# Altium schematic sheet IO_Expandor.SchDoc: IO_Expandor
size A3; DocumentNumber: MB1144; Revision: B-02; SheetNumber: 6; SheetTotal: 25; Project: STM32L476G-EVAL
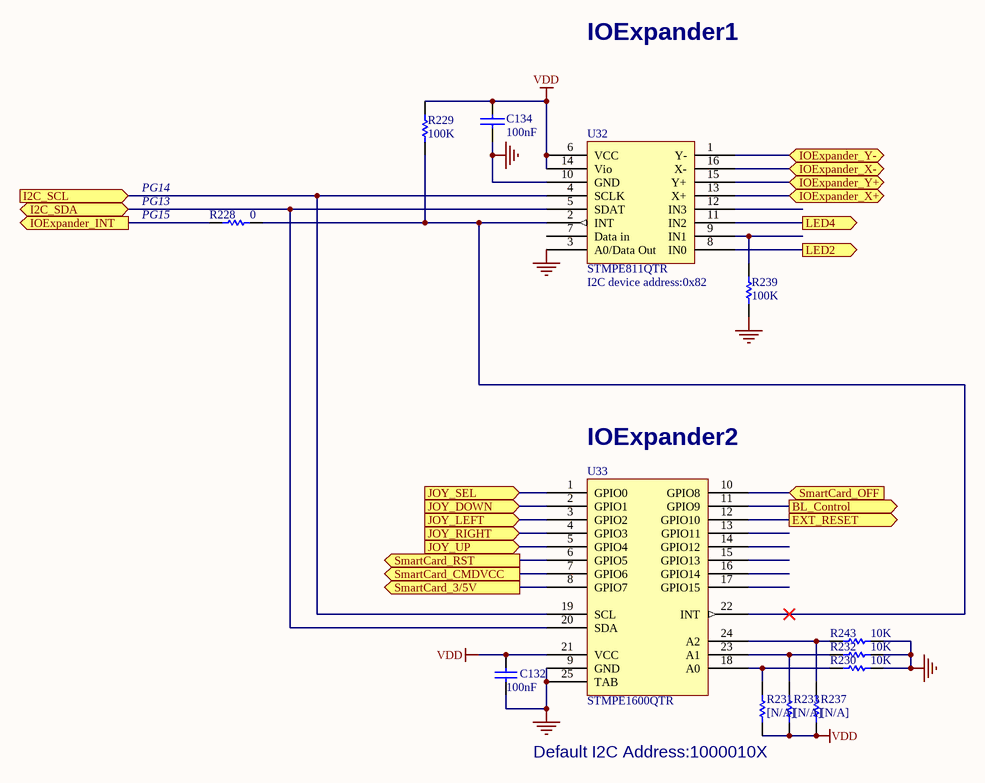
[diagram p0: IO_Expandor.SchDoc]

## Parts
C132  100nF  [0402C]
C134  100nF  [0402C]
R228  0  [0603R]
R229  100K  [0402R]
R230  10K  [0402R]
R231  [N/A]  [0603R]
R232  10K  [0402R]
R233  [N/A]  [0603R]
R237  [N/A]  [0603R]
R239  100K  [0402R]
R243  10K  [0402R]
U32  STMPE811QTR  [QFN16_0R5_3X3]
U33  STMPE1600QTR  [QFN24_0R5_4X4]

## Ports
BL_Control (out), EXT_RESET (out), I2C_SCL (in), I2C_SDA (bidir), IOExpander_INT (out), IOExpander_X+ (bidir), IOExpander_X- (bidir), IOExpander_Y+ (bidir), IOExpander_Y- (bidir), JOY_DOWN (in), JOY_LEFT (in), JOY_RIGHT (in), JOY_SEL (in), JOY_UP (in), LED2 (out), LED4 (out), SmartCard_3/5V (out), SmartCard_CMDVCC (out), SmartCard_OFF (in), SmartCard_RST (out)

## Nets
GND: C132.2 C134.2 R230.1 R232.1 R239.2 R243.1 U32.3(A0/Data_Out) U32.10(GND) U33.9(GND) U33.25(TAB)
VDD: C132.1 C134.1 R229.1 R231.1 R233.1 R237.1 U32.6(VCC) U32.14(Vio) U33.21(VCC)
BL_Control: U33.11(GPIO9) ; port BL_Control
EXT_RESET: U33.12(GPIO10) ; port EXT_RESET
I2C_SCL: U32.4(SCLK) U33.19(SCL) ; port I2C_SCL
I2C_SDA: U32.5(SDAT) U33.20(SDA) ; port I2C_SDA
IOExpander_INT: R228.1 ; port IOExpander_INT
IOExpander_X+: U32.13(X+) ; port IOExpander_X+
IOExpander_X-: U32.16(X-) ; port IOExpander_X-
IOExpander_Y+: U32.15(Y+) ; port IOExpander_Y+
IOExpander_Y-: U32.1(Y-) ; port IOExpander_Y-
JOY_DOWN: U33.2(GPIO1) ; port JOY_DOWN
JOY_LEFT: U33.3(GPIO2) ; port JOY_LEFT
JOY_RIGHT: U33.4(GPIO3) ; port JOY_RIGHT
JOY_SEL: U33.1(GPIO0) ; port JOY_SEL
JOY_UP: U33.5(GPIO4) ; port JOY_UP
LED2: U32.8(IN0) ; port LED2
LED4: U32.11(IN2) ; port LED4
SmartCard_3/5V: U33.8(GPIO7) ; port SmartCard_3/5V
SmartCard_CMDVCC: U33.7(GPIO6) ; port SmartCard_CMDVCC
SmartCard_OFF: U33.10(GPIO8) ; port SmartCard_OFF
SmartCard_RST: U33.6(GPIO5) ; port SmartCard_RST
NetR228_2: R228.2 R229.2 U32.2(INT) U33.22(INT)
NetR230_2: R230.2 R231.2 U33.18(A0)
NetR232_2: R232.2 R233.2 U33.23(A1)
NetR237_2: R237.2 R243.2 U33.24(A2)
NetR239_1: R239.1 U32.9(IN1)

Not connected (* = marked no-connect by the designer): U32 7(Data_in) 12(IN3); U33 13(GPIO11) 14(GPIO12) 15(GPIO13) 16(GPIO14) 17(GPIO15)

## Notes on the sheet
- IOExpander1
- PG13
- PG14
- PG15
- I2C device address:0x82
- (near U33) IOExpander2
- Default I2C Address:1000010X

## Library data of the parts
C132 = Cap: Capacitor; Value: 10nF; Ordered by: Subcon; ECCN_US/EU: NA
C134 = CAP: Capacitor; Ordered by: Subcon; ECCN_US/EU: NA
R228 R229 R239 = Res1: Resistor; Value: 1K; Ordered by: Subcon; ECCN_US/EU: NA
R230 R232 R243 = res1: Resistor; Value: 1K; Ordered by: Subcon; ECCN_US/EU: NA
R231 R233 R237 = Res1: Resistor; Value: 1K; Ordered by: Subcon; ECCN_US/EU: NA; Fitted: NO
U32 = STMPE811: Ordered by: ST; ECCN_US/EU: EAR99/NEC; Ref St: 9177945
U33 = STMPE1600: Ordered by: ST; ECCN_US/EU: EAR99/NEC; Ref St: 9177976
